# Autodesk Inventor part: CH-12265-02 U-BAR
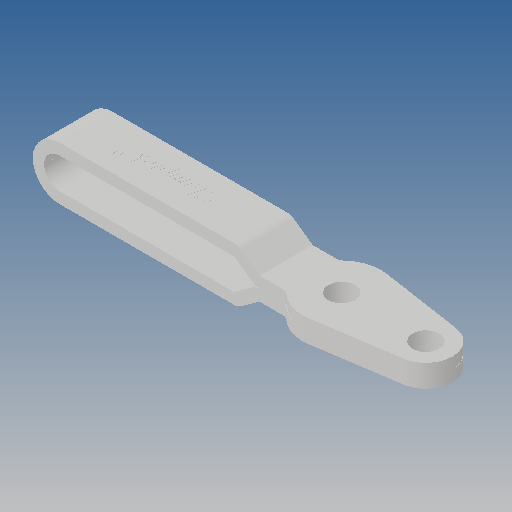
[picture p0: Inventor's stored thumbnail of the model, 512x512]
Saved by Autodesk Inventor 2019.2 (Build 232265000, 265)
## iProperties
Created: 2012-09
Part Number: CH-12265-02 U-BAR
Material: Ogólny
Document SubType Name: Modeling
Designer: CADENGINEERING4
Density: 1 g/cm^3
Appearance: Domyślna
Author: CADENGINEERING4
Revision Number: ÈÎºÎ
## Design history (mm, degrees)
feature "ÇÐ³ý-À­Éì2"
feature "ÇÐ³ý-À­Éì5"
node "Bryła1"
node "Bryła2"
